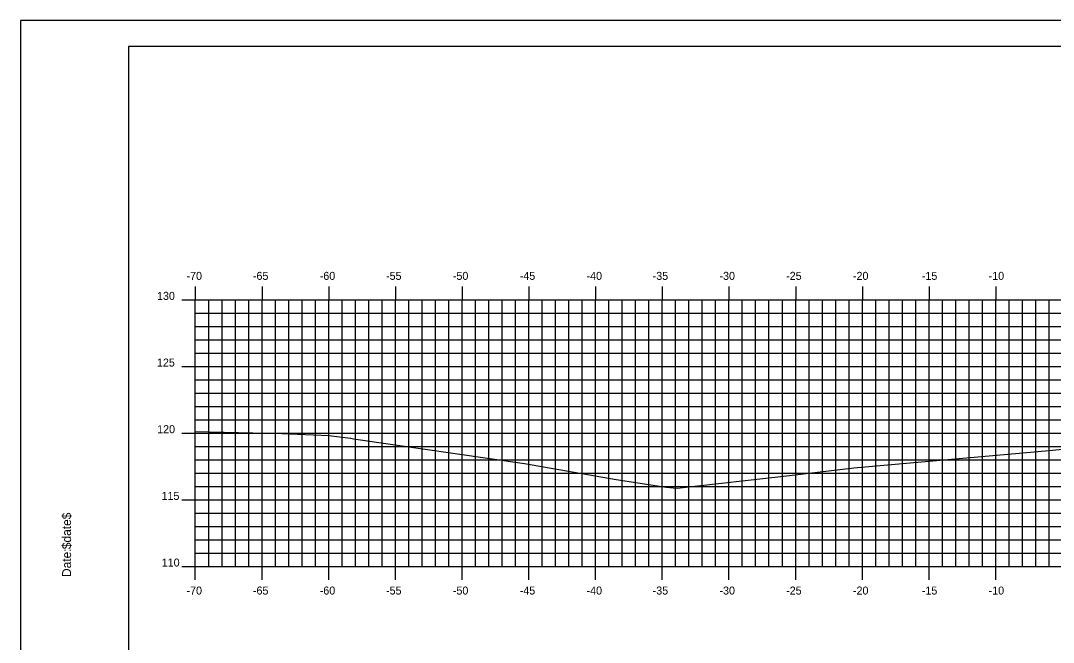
# Model space of a CAD drawing. Extents: x 853069 to 853241, y 365624 to 365734.
# Drawn here: x 853069 to 853146.4, y 365687.3 to 365734 of the extents above; entities that cross this region are included whole.
import ezdxf

# ---------------------------------------------------------------- set-up
doc = ezdxf.new("R2010")
doc.units = 0
for name, color, linetype in [('BORDER', 7, 'Continuous'), ('H_V ANNOTATION', 7, 'Continuous'), ('MAJOR', 7, 'Continuous'), ('MINOR', 7, 'Continuous'), ('PLOT BOUNDARY', 7, 'Continuous'), ('S_Roadway_Centerline', 7, 'Continuous')]:
    doc.layers.add(name, color=color, linetype=linetype)

msp = doc.modelspace()

# ---------------------------------------------------------------- linework, layer by layer
at = {"layer": 'BORDER'}
msp.add_lwpolyline([(853077.062, 365627.027), (853237.062, 365627.027), (853237.062, 365732.027), (853077.062, 365732.027)], close=True, dxfattribs=at)
at = {"layer": 'MAJOR'}
for p, q in [((853082.061, 365714.029), (853082.061, 365713.027)), ((853087.061, 365714.029), (853087.061, 365713.027)), ((853092.061, 365714.029), (853092.061, 365713.027)), ((853097.061, 365714.029), (853097.061, 365713.027)), ((853102.061, 365714.029), (853102.061, 365713.027)), ((853107.061, 365714.029), (853107.061, 365713.027)), ((853112.061, 365714.029), (853112.061, 365713.027)), ((853117.061, 365714.029), (853117.061, 365713.027)), ((853122.061, 365714.029), (853122.061, 365713.027)), ((853127.061, 365714.029), (853127.061, 365713.027)), ((853132.061, 365714.029), (853132.061, 365713.027)), ((853137.061, 365714.029), (853137.061, 365713.027)), ((853142.061, 365714.029), (853142.061, 365713.027)), ((853081.059, 365713.027), (853082.061, 365713.027)), ((853082.061, 365713.027), (853222.061, 365713.027)), ((853082.061, 365693.027), (853082.061, 365713.027)), ((853082.061, 365693.027), (853082.061, 365713.027)), ((853082.061, 365713.027), (853222.061, 365713.027)), ((853087.061, 365693.027), (853087.061, 365713.027)), ((853092.061, 365693.027), (853092.061, 365713.027)), ((853097.061, 365693.027), (853097.061, 365713.027)), ((853102.061, 365693.027), (853102.061, 365713.027)), ((853107.061, 365693.027), (853107.061, 365713.027)), ((853112.061, 365693.027), (853112.061, 365713.027)), ((853117.061, 365693.027), (853117.061, 365713.027)), ((853122.061, 365693.027), (853122.061, 365713.027)), ((853127.061, 365693.027), (853127.061, 365713.027)), ((853132.061, 365693.027), (853132.061, 365713.027)), ((853137.061, 365693.027), (853137.061, 365713.027)), ((853142.061, 365693.027), (853142.061, 365713.027)), ((853081.059, 365708.027), (853082.061, 365708.027)), ((853082.061, 365708.027), (853222.061, 365708.027)), ((853081.059, 365703.027), (853082.061, 365703.027)), ((853082.061, 365703.027), (853222.061, 365703.027)), ((853081.059, 365698.027), (853082.061, 365698.027)), ((853082.061, 365698.027), (853222.061, 365698.027)), ((853081.059, 365693.027), (853082.061, 365693.027)), ((853082.061, 365693.027), (853222.061, 365693.027)), ((853082.061, 365693.027), (853222.061, 365693.027)), ((853082.061, 365692.025), (853082.061, 365693.027)), ((853087.061, 365692.025), (853087.061, 365693.027)), ((853092.061, 365692.025), (853092.061, 365693.027)), ((853097.061, 365692.025), (853097.061, 365693.027)), ((853102.061, 365692.025), (853102.061, 365693.027)), ((853107.061, 365692.025), (853107.061, 365693.027)), ((853112.061, 365692.025), (853112.061, 365693.027)), ((853117.061, 365692.025), (853117.061, 365693.027)), ((853122.061, 365692.025), (853122.061, 365693.027)), ((853127.061, 365692.025), (853127.061, 365693.027)), ((853132.061, 365692.025), (853132.061, 365693.027)), ((853137.061, 365692.025), (853137.061, 365693.027)), ((853142.061, 365692.025), (853142.061, 365693.027))]:
    msp.add_line(p, q, dxfattribs=at)
at = {"layer": 'MINOR'}
for p, q in [((853083.061, 365693.027), (853083.061, 365713.027)), ((853084.061, 365693.027), (853084.061, 365713.027)), ((853085.061, 365693.027), (853085.061, 365713.027)), ((853086.061, 365693.027), (853086.061, 365713.027)), ((853088.061, 365693.027), (853088.061, 365713.027)), ((853089.061, 365693.027), (853089.061, 365713.027)), ((853090.061, 365693.027), (853090.061, 365713.027)), ((853091.061, 365693.027), (853091.061, 365713.027)), ((853093.061, 365693.027), (853093.061, 365713.027)), ((853094.061, 365693.027), (853094.061, 365713.027)), ((853095.061, 365693.027), (853095.061, 365713.027)), ((853096.061, 365693.027), (853096.061, 365713.027)), ((853098.061, 365693.027), (853098.061, 365713.027)), ((853099.061, 365693.027), (853099.061, 365713.027)), ((853100.061, 365693.027), (853100.061, 365713.027)), ((853101.061, 365693.027), (853101.061, 365713.027)), ((853103.061, 365693.027), (853103.061, 365713.027)), ((853104.061, 365693.027), (853104.061, 365713.027)), ((853105.061, 365693.027), (853105.061, 365713.027)), ((853106.061, 365693.027), (853106.061, 365713.027)), ((853108.061, 365693.027), (853108.061, 365713.027)), ((853109.061, 365693.027), (853109.061, 365713.027)), ((853110.061, 365693.027), (853110.061, 365713.027)), ((853111.061, 365693.027), (853111.061, 365713.027)), ((853113.061, 365693.027), (853113.061, 365713.027)), ((853114.061, 365693.027), (853114.061, 365713.027)), ((853115.061, 365693.027), (853115.061, 365713.027)), ((853116.061, 365693.027), (853116.061, 365713.027)), ((853118.061, 365693.027), (853118.061, 365713.027)), ((853119.061, 365693.027), (853119.061, 365713.027)), ((853120.061, 365693.027), (853120.061, 365713.027)), ((853121.061, 365693.027), (853121.061, 365713.027)), ((853123.061, 365693.027), (853123.061, 365713.027)), ((853124.061, 365693.027), (853124.061, 365713.027)), ((853125.061, 365693.027), (853125.061, 365713.027)), ((853126.061, 365693.027), (853126.061, 365713.027)), ((853128.061, 365693.027), (853128.061, 365713.027)), ((853129.061, 365693.027), (853129.061, 365713.027)), ((853130.061, 365693.027), (853130.061, 365713.027)), ((853131.061, 365693.027), (853131.061, 365713.027)), ((853133.061, 365693.027), (853133.061, 365713.027)), ((853134.061, 365693.027), (853134.061, 365713.027)), ((853135.061, 365693.027), (853135.061, 365713.027)), ((853136.061, 365693.027), (853136.061, 365713.027)), ((853138.061, 365693.027), (853138.061, 365713.027)), ((853139.061, 365693.027), (853139.061, 365713.027)), ((853140.061, 365693.027), (853140.061, 365713.027)), ((853141.061, 365693.027), (853141.061, 365713.027)), ((853143.061, 365693.027), (853143.061, 365713.027)), ((853144.061, 365693.027), (853144.061, 365713.027)), ((853145.061, 365693.027), (853145.061, 365713.027)), ((853146.061, 365693.027), (853146.061, 365713.027)), ((853082.061, 365712.027), (853222.061, 365712.027)), ((853082.061, 365712.027), (853083.063, 365712.027)), ((853082.061, 365711.027), (853222.061, 365711.027)), ((853082.061, 365711.027), (853083.063, 365711.027)), ((853082.061, 365710.027), (853222.061, 365710.027)), ((853082.061, 365710.027), (853083.063, 365710.027)), ((853082.061, 365709.027), (853222.061, 365709.027)), ((853082.061, 365709.027), (853083.063, 365709.027)), ((853082.061, 365707.027), (853222.061, 365707.027)), ((853082.061, 365707.027), (853083.063, 365707.027)), ((853082.061, 365706.027), (853222.061, 365706.027)), ((853082.061, 365706.027), (853083.063, 365706.027)), ((853082.061, 365705.027), (853222.061, 365705.027)), ((853082.061, 365705.027), (853083.063, 365705.027)), ((853082.061, 365704.027), (853222.061, 365704.027)), ((853082.061, 365704.027), (853083.063, 365704.027)), ((853082.061, 365702.027), (853222.061, 365702.027)), ((853082.061, 365702.027), (853083.063, 365702.027)), ((853082.061, 365701.027), (853222.061, 365701.027)), ((853082.061, 365701.027), (853083.063, 365701.027)), ((853082.061, 365700.027), (853222.061, 365700.027)), ((853082.061, 365700.027), (853083.063, 365700.027)), ((853082.061, 365699.027), (853222.061, 365699.027)), ((853082.061, 365699.027), (853083.063, 365699.027)), ((853082.061, 365697.027), (853222.061, 365697.027)), ((853082.061, 365697.027), (853083.063, 365697.027)), ((853082.061, 365696.027), (853222.061, 365696.027)), ((853082.061, 365696.027), (853083.063, 365696.027)), ((853082.061, 365695.027), (853222.061, 365695.027)), ((853082.061, 365695.027), (853083.063, 365695.027)), ((853082.061, 365694.027), (853222.061, 365694.027)), ((853082.061, 365694.027), (853083.063, 365694.027))]:
    msp.add_line(p, q, dxfattribs=at)
at = {"layer": 'PLOT BOUNDARY'}
msp.add_lwpolyline([(853068.968, 365623.968), (853238.968, 365623.968), (853238.968, 365733.968), (853068.968, 365733.968)], close=True, dxfattribs=at)
at = {"layer": 'S_Roadway_Centerline'}
msp.add_lwpolyline([(853082.061, 365703.157), (853088.548, 365702.997), (853092.078, 365702.862), (853093.69, 365702.65), (853093.726, 365702.646), (853093.912, 365702.617), (853106.738, 365700.763), (853113.613, 365699.56), (853117.36, 365698.972), (853118.187, 365698.908), (853126.589, 365699.855), (853131.416, 365700.432), (853146.06, 365701.731), (853151.328, 365702.256)], dxfattribs=at)

# ---------------------------------------------------------------- texts
at = {"layer": 'BORDER'}
for s, p in [('$date$', (853072.747, 365694.332)), ('Date:', (853072.747, 365692.244))]:
    msp.add_text(s, height=0.6696, rotation=90, dxfattribs=at).set_placement(p)
at = {"layer": 'H_V ANNOTATION'}
for s, p in [('-70', (853081.403, 365714.527)), ('-65', (853086.379, 365714.527)), ('-60', (853091.387, 365714.527)), ('-55', (853096.358, 365714.527)), ('-50', (853101.366, 365714.527)), ('-45', (853106.379, 365714.527)), ('-40', (853111.387, 365714.527)), ('-35', (853116.342, 365714.527)), ('-30', (853121.35, 365714.527)), ('-25', (853126.347, 365714.527)), ('-20', (853131.355, 365714.527)), ('-15', (853136.518, 365714.527)), ('-10', (853141.526, 365714.527)), ('130', (853079.191, 365713.027)), ('125', (853079.186, 365708.027)), ('120', (853079.202, 365703.027)), ('115', (853079.529, 365698.027)), ('110', (853079.545, 365693.027)), ('-70', (853081.403, 365690.927)), ('-65', (853086.379, 365690.927)), ('-60', (853091.387, 365690.927)), ('-55', (853096.358, 365690.927)), ('-50', (853101.366, 365690.927)), ('-45', (853106.379, 365690.927)), ('-40', (853111.387, 365690.927)), ('-35', (853116.342, 365690.927)), ('-30', (853121.35, 365690.927)), ('-25', (853126.347, 365690.927)), ('-20', (853131.355, 365690.927)), ('-15', (853136.518, 365690.927)), ('-10', (853141.526, 365690.927))]:
    msp.add_text(s, height=0.6, dxfattribs=at).set_placement(p)
at = {"layer": 'MAJOR'}
msp.add_text('-', height=0.006, dxfattribs=at).set_placement((853082.057, 365693.027))

doc.saveas('drawing.dxf')
